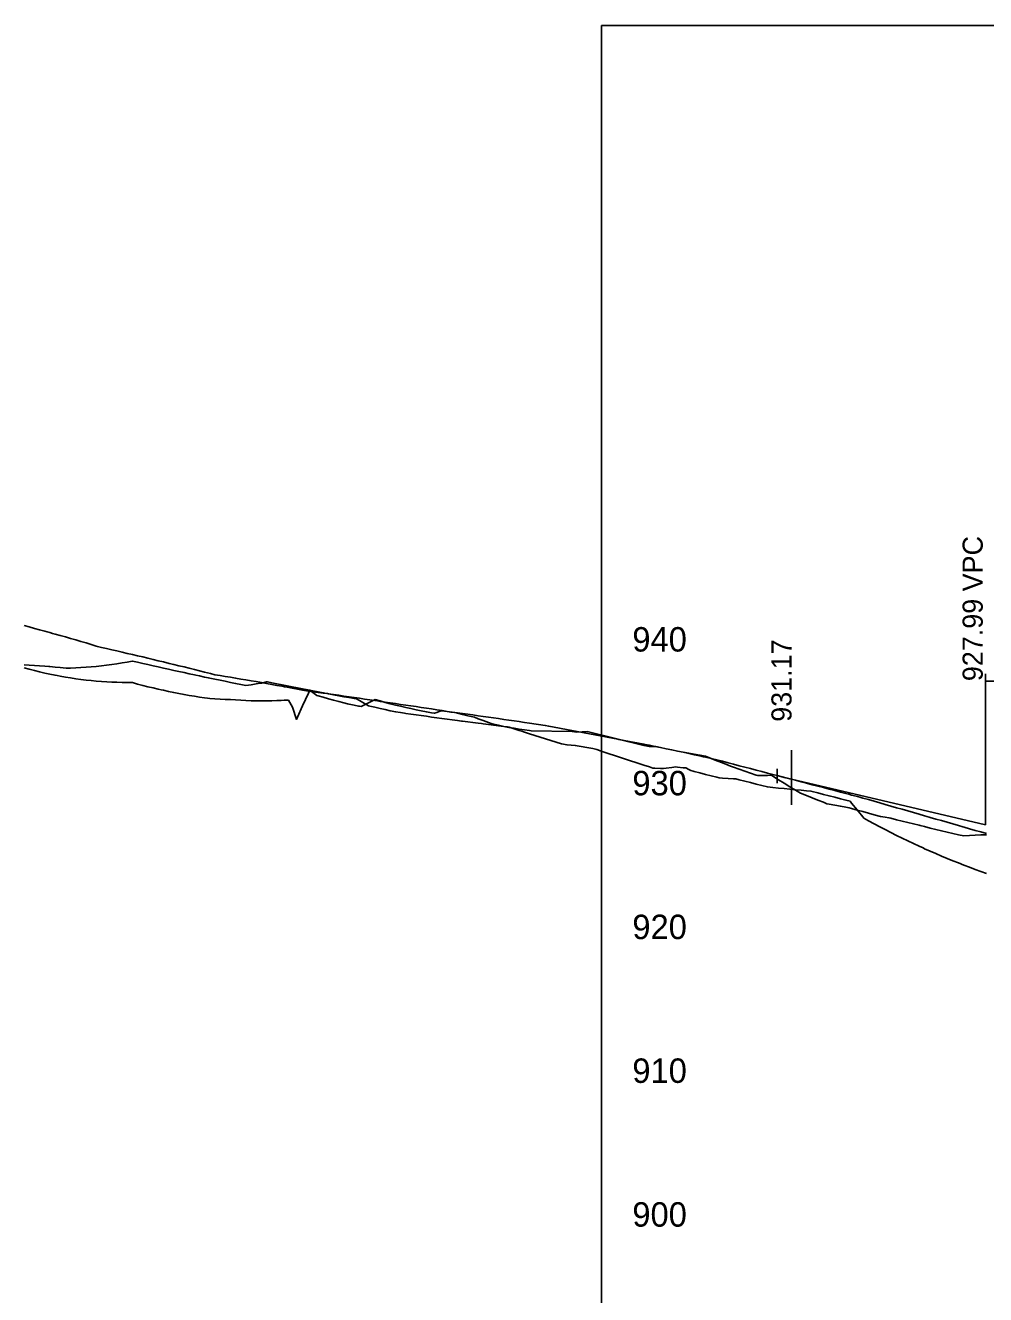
# Model space of a CAD drawing. Extents: x 1538426 to 1542651, y 1162537 to 1163637.
# Drawn here: x 1539359.4 to 1539693.4, y 1163195.3 to 1163636.7 of the extents above; entities that cross this region are included whole.
import ezdxf

# ---------------------------------------------------------------- set-up
doc = ezdxf.new("R2010")
doc.units = 0
for name, color, linetype in [('BR_EXIST_GROUND_LT', 7, 'Continuous'), ('BR_EXIST_GROUND_RT', 7, 'Continuous'), ('BR_USER NOTES', 7, 'Continuous'), ('RD_DDB_ElevTX', 7, 'Continuous'), ('RD_DDB_Profile_EX', 7, 'Continuous'), ('RD_DDB_Profile_Lbl', 7, 'Continuous'), ('RD_DDB_Profile_PR', 7, 'Continuous'), ('RD_DDB_StripGrade', 7, 'Continuous'), ('RD_DDB_VCLbl', 7, 'Continuous'), ('RD_SHT_ShtClip', 7, 'Continuous')]:
    doc.layers.add(name, color=color, linetype=linetype)

msp = doc.modelspace()

# ---------------------------------------------------------------- linework, layer by layer
at = {"layer": 'BR_EXIST_GROUND_LT'}
msp.add_lwpolyline([(1539358.99, 1163414.41), (1539360.78, 1163414.24), (1539362.58, 1163414.09), (1539364.37, 1163413.97), (1539366.16, 1163413.86), (1539367.57, 1163413.8), (1539367.96, 1163413.75), (1539369.75, 1163413.55), (1539371.55, 1163413.37), (1539373.64, 1163413.19), (1539375.14, 1163413.23), (1539376.93, 1163413.29), (1539378.72, 1163413.39), (1539380.52, 1163413.5), (1539382.31, 1163413.64), (1539384.11, 1163413.81), (1539385.9, 1163414), (1539387.69, 1163414.21), (1539389.49, 1163414.45), (1539391.28, 1163414.72), (1539393.08, 1163415.01), (1539394.87, 1163415.32), (1539396.6, 1163415.64), (1539397.27, 1163415.51), (1539398.46, 1163415.24), (1539400.25, 1163414.83), (1539402.05, 1163414.42), (1539403.84, 1163414.02), (1539405.64, 1163413.62), (1539407.43, 1163413.22), (1539409.22, 1163412.83), (1539411.02, 1163412.43), (1539412.81, 1163412.04), (1539414.61, 1163411.66), (1539416.4, 1163411.27), (1539418.2, 1163410.89), (1539418.67, 1163410.79), (1539419.99, 1163410.5), (1539421.78, 1163410.11), (1539423.1, 1163409.83), (1539423.58, 1163409.73), (1539425.37, 1163409.36), (1539427.17, 1163408.99), (1539428.96, 1163408.62), (1539430.75, 1163408.25), (1539432.55, 1163407.89), (1539434.34, 1163407.53), (1539436.14, 1163407.18), (1539437.93, 1163407.44), (1539439.74, 1163407.7), (1539441.2, 1163407.92), (1539441.52, 1163408.03), (1539443.31, 1163408.49), (1539443.67, 1163408.43), (1539445.11, 1163408.15), (1539446.9, 1163407.79), (1539448.7, 1163407.44), (1539450.49, 1163407.09), (1539452.28, 1163406.74), (1539454.08, 1163406.39), (1539455.87, 1163406.04), (1539457.67, 1163405.7), (1539459.46, 1163405.35), (1539461.26, 1163405), (1539463.05, 1163404.66), (1539464.84, 1163404.31), (1539466.64, 1163403.97), (1539468.43, 1163403.62), (1539470.23, 1163403.28), (1539472.02, 1163402.94), (1539473.81, 1163402.64), (1539474.64, 1163402.51), (1539475.61, 1163401.94), (1539477.4, 1163400.9), (1539478.77, 1163400.1), (1539479.2, 1163400.02), (1539480.99, 1163399.61), (1539482.79, 1163399.2), (1539484.58, 1163398.79), (1539486.37, 1163398.38), (1539487.02, 1163398.23), (1539488.17, 1163398.05), (1539489.96, 1163397.75), (1539491.27, 1163397.54), (1539491.76, 1163397.47), (1539493.55, 1163397.21), (1539495.34, 1163396.95), (1539497.14, 1163396.7), (1539498.93, 1163396.45), (1539500.73, 1163396.2), (1539502.52, 1163395.96), (1539504.32, 1163395.71), (1539506.11, 1163395.47), (1539507.9, 1163395.24), (1539509.7, 1163395), (1539511.17, 1163394.81), (1539511.49, 1163394.77), (1539513.29, 1163394.54), (1539515.08, 1163394.32), (1539516.87, 1163394.1), (1539518.09, 1163393.95), (1539518.67, 1163393.87), (1539520.46, 1163393.63), (1539522.26, 1163393.4), (1539524.05, 1163393.18), (1539525.85, 1163392.96), (1539527.1, 1163392.81), (1539527.68, 1163392.67), (1539529.43, 1163392.1), (1539531.23, 1163391.52), (1539532.1, 1163391.24), (1539533.02, 1163390.94), (1539534.82, 1163390.35), (1539545.94, 1163386.89), (1539547.84, 1163386.53), (1539550.66, 1163386.35), (1539556.76, 1163385.2), (1539558.19, 1163384.86), (1539559.71, 1163384.28), (1539574.51, 1163379.5), (1539576.47, 1163378.86), (1539577.7, 1163378.46), (1539578.42, 1163378.43), (1539580.38, 1163378.36), (1539581.41, 1163378.34), (1539582.33, 1163378.43), (1539584.28, 1163378.65), (1539585.73, 1163378.83), (1539586.24, 1163378.77), (1539588.19, 1163378.58), (1539589.18, 1163378.48), (1539590.15, 1163378), (1539590.91, 1163377.62), (1539591.69, 1163377.36), (1539592.1, 1163377.26), (1539594.06, 1163376.76), (1539596.01, 1163376.27), (1539597.96, 1163375.78), (1539599.92, 1163375.27), (1539600.75, 1163375.06), (1539601.87, 1163374.99), (1539603.83, 1163374.87), (1539605.78, 1163374.75), (1539606.52, 1163374.71), (1539607.73, 1163374.39), (1539609.69, 1163373.89), (1539611.64, 1163373.39), (1539613.6, 1163372.89), (1539615.55, 1163372.4), (1539617.51, 1163371.92), (1539619.46, 1163371.72), (1539621.41, 1163371.52), (1539623.37, 1163371.33), (1539625.32, 1163371.13), (1539627.28, 1163370.94), (1539629.23, 1163370.75), (1539631.18, 1163370.57), (1539632.66, 1163370.44), (1539633.14, 1163370.31), (1539635.09, 1163369.8), (1539637.05, 1163369.3), (1539639, 1163368.79), (1539640.96, 1163368.29), (1539642.91, 1163367.79), (1539644.86, 1163367.29), (1539646.26, 1163366.93), (1539646.82, 1163366.26), (1539648.77, 1163363.9), (1539649.2, 1163363.39), (1539650.73, 1163361.48), (1539651.08, 1163361.04), (1539652.68, 1163360.16), (1539654.63, 1163359.11), (1539656.59, 1163358.07), (1539658.54, 1163357.05), (1539660.5, 1163356.05), (1539662.45, 1163355.06), (1539664.41, 1163354.1), (1539666.36, 1163353.15), (1539668.31, 1163352.22), (1539670.27, 1163351.31), (1539671.7, 1163350.66), (1539672.22, 1163350.42), (1539674.18, 1163349.55), (1539676.13, 1163348.69), (1539678.08, 1163347.85), (1539680.04, 1163347.04), (1539681.99, 1163346.24), (1539683.95, 1163345.46), (1539685.9, 1163344.69), (1539687.86, 1163343.95), (1539689.81, 1163343.22), (1539691.76, 1163342.52), (1539693.72, 1163341.83)], dxfattribs=at)
at = {"layer": 'BR_EXIST_GROUND_RT'}
msp.add_lwpolyline([(1539358.99, 1163413.31), (1539360.78, 1163412.82), (1539362.58, 1163412.35), (1539364.37, 1163411.91), (1539366.16, 1163411.5), (1539367.96, 1163411.11), (1539369.75, 1163410.74), (1539370.52, 1163410.59), (1539371.55, 1163410.4), (1539373.34, 1163410.08), (1539375.14, 1163409.79), (1539376.93, 1163409.53), (1539378.72, 1163409.28), (1539380.52, 1163409.06), (1539382.31, 1163408.87), (1539384.11, 1163408.7), (1539385.9, 1163408.55), (1539387.78, 1163408.42), (1539389.49, 1163408.34), (1539391.28, 1163408.27), (1539393.08, 1163408.22), (1539394.87, 1163408.2), (1539396.67, 1163408.16), (1539398.46, 1163407.66), (1539400.25, 1163407.18), (1539402.05, 1163406.73), (1539403.84, 1163406.3), (1539405.64, 1163405.9), (1539406.66, 1163405.68), (1539407.43, 1163405.5), (1539409.22, 1163405.09), (1539411.02, 1163404.71), (1539412.81, 1163404.34), (1539414.61, 1163404.01), (1539416.4, 1163403.69), (1539418.2, 1163403.4), (1539419.99, 1163403.13), (1539421.78, 1163402.88), (1539422.74, 1163402.77), (1539423.58, 1163402.69), (1539425.37, 1163402.55), (1539427.17, 1163402.43), (1539428.96, 1163402.34), (1539430.75, 1163402.27), (1539432.55, 1163402.14), (1539434.34, 1163402.04), (1539436.14, 1163401.95), (1539437.93, 1163401.89), (1539439.73, 1163401.85), (1539441.52, 1163401.83), (1539443.31, 1163401.83), (1539445.11, 1163401.86), (1539446.9, 1163401.9), (1539448.42, 1163401.96), (1539449.4, 1163402.01), (1539450.49, 1163402.08), (1539450.95, 1163402.11), (1539452.38, 1163399.67), (1539453.75, 1163395.38), (1539454.08, 1163396.12), (1539455.87, 1163400.09), (1539457.87, 1163404.53), (1539458.35, 1163405.6), (1539459.46, 1163404.78), (1539460.82, 1163403.72), (1539461.26, 1163403.59), (1539463.05, 1163403.08), (1539464.84, 1163402.58), (1539466.64, 1163402.08), (1539468.43, 1163401.58), (1539470.23, 1163401.09), (1539471.46, 1163400.75), (1539472.02, 1163400.63), (1539473.81, 1163400.27), (1539475.3, 1163399.97), (1539475.61, 1163399.95), (1539476.19, 1163399.91), (1539477.4, 1163400.49), (1539479.2, 1163401.36), (1539481.07, 1163402.28), (1539482.79, 1163401.8), (1539484.58, 1163401.31), (1539486.37, 1163400.83), (1539488.17, 1163400.38), (1539489.96, 1163399.94), (1539491.76, 1163399.52), (1539493.55, 1163399.11), (1539495.34, 1163398.73), (1539497.14, 1163398.35), (1539498.93, 1163398), (1539500.73, 1163397.66), (1539501.73, 1163397.49), (1539502.52, 1163397.75), (1539503.98, 1163398.38), (1539504.32, 1163398.33), (1539506.11, 1163398.07), (1539507.9, 1163397.84), (1539509.4, 1163397.67), (1539509.7, 1163397.58), (1539511.49, 1163397.12), (1539513.29, 1163396.67), (1539515.08, 1163396.25), (1539515.65, 1163396.12), (1539516.87, 1163395.63), (1539518.67, 1163394.94), (1539520.46, 1163394.27), (1539521.4, 1163393.94), (1539522.26, 1163393.74), (1539524.05, 1163393.34), (1539525.85, 1163392.96), (1539527.64, 1163392.61), (1539529.43, 1163392.29), (1539531.23, 1163391.99), (1539533.02, 1163391.72), (1539534.82, 1163391.47), (1539535.3, 1163391.41), (1539549.63, 1163391.21), (1539551.26, 1163390.99), (1539554.8, 1163391.18), (1539574.51, 1163386.33), (1539576.47, 1163385.91), (1539578.7, 1163385.93), (1539580.38, 1163385.57), (1539582.33, 1163385.15), (1539584.28, 1163384.76), (1539586.24, 1163384.37), (1539588.19, 1163384), (1539590.15, 1163383.64), (1539592.1, 1163383.29), (1539594.06, 1163382.96), (1539596.01, 1163382.62), (1539597.96, 1163381.82), (1539599.92, 1163381.02), (1539601.87, 1163380.24), (1539603.83, 1163379.47), (1539604.72, 1163379.13), (1539605.78, 1163378.74), (1539607.73, 1163378.05), (1539609.69, 1163377.36), (1539611.64, 1163376.69), (1539613.6, 1163376.03), (1539614.07, 1163375.88), (1539615.55, 1163375.89), (1539617.51, 1163375.92), (1539618.9, 1163375.95), (1539619.46, 1163375.6), (1539621.41, 1163374.36), (1539623.37, 1163373.15), (1539625.32, 1163371.97), (1539627.28, 1163370.8), (1539629.08, 1163369.76), (1539631.18, 1163368.88), (1539633.14, 1163368.09), (1539635.09, 1163367.31), (1539637.05, 1163366.54), (1539638.25, 1163366.07), (1539639, 1163365.93), (1539640.96, 1163365.56), (1539642.91, 1163365.19), (1539644.86, 1163364.84), (1539645.97, 1163364.65), (1539646.82, 1163364.4), (1539648.77, 1163363.85), (1539650.73, 1163363.31), (1539652.68, 1163362.77), (1539654.63, 1163362.24), (1539656.82, 1163361.66), (1539658.54, 1163361.38), (1539659.8, 1163361.18), (1539660.5, 1163361), (1539662.45, 1163360.5), (1539664.41, 1163360.01), (1539666.36, 1163359.53), (1539668.31, 1163359.06), (1539670.27, 1163358.59), (1539670.64, 1163358.5), (1539672.22, 1163358.1), (1539674.18, 1163357.61), (1539676.13, 1163357.13), (1539678.08, 1163356.66), (1539680.04, 1163356.19), (1539681.99, 1163355.72), (1539683.95, 1163355.27), (1539685.9, 1163354.9), (1539687.86, 1163354.98), (1539689.81, 1163355.08), (1539691.76, 1163355.18), (1539693.72, 1163355.29)], dxfattribs=at)
at = {"layer": 'BR_USER NOTES'}
for p, q in [((1539625.92, 1163384.65), (1539625.92, 1163365.69)), ((1539620.92, 1163378.13), (1539620.92, 1163373.15)), ((1539620.92, 1163375.84), (1539625.92, 1163374.55))]:
    msp.add_line(p, q, dxfattribs=at)
at = {"layer": 'RD_DDB_Profile_EX'}
msp.add_lwpolyline([(1539358.99, 1163428.02), (1539360.78, 1163427.52), (1539362.58, 1163427.03), (1539364.37, 1163426.53), (1539366.16, 1163426.03), (1539367.02, 1163425.79), (1539367.96, 1163425.55), (1539368.89, 1163425.3), (1539369.75, 1163425.06), (1539371.55, 1163424.56), (1539373.34, 1163424.06), (1539375.14, 1163423.55), (1539376.93, 1163423.05), (1539377.68, 1163422.84), (1539378.72, 1163422.52), (1539380.52, 1163421.96), (1539382.31, 1163421.41), (1539384.11, 1163420.85), (1539384.51, 1163420.72), (1539385.9, 1163420.4), (1539387.69, 1163420), (1539389.49, 1163419.59), (1539391.28, 1163419.18), (1539393.08, 1163418.77), (1539394.87, 1163418.35), (1539396.67, 1163417.93), (1539398.46, 1163417.51), (1539400.25, 1163417.09), (1539402.05, 1163416.66), (1539403.84, 1163416.23), (1539405.64, 1163415.8), (1539407.43, 1163415.37), (1539409.5, 1163414.86), (1539411.02, 1163414.49), (1539412.81, 1163414.05), (1539414.61, 1163413.6), (1539416.4, 1163413.15), (1539418.2, 1163412.7), (1539419.99, 1163412.25), (1539421.78, 1163411.79), (1539423.77, 1163411.29), (1539425.37, 1163410.88), (1539427.17, 1163410.6), (1539428.96, 1163410.31), (1539430.75, 1163410.02), (1539432.55, 1163409.72), (1539434.34, 1163409.42), (1539436.14, 1163409.12), (1539437.93, 1163408.81), (1539439.73, 1163408.5), (1539441.52, 1163408.18), (1539443.31, 1163407.86), (1539445.11, 1163407.54), (1539446.9, 1163407.21), (1539448.7, 1163406.88), (1539449.26, 1163406.78), (1539449.59, 1163406.73), (1539450.49, 1163406.56), (1539452.28, 1163406.22), (1539454.08, 1163405.88), (1539455.87, 1163405.54), (1539457.89, 1163405.15), (1539459.46, 1163404.96), (1539461.26, 1163404.75), (1539463.05, 1163404.52), (1539464.46, 1163404.34), (1539464.84, 1163404.29), (1539466.64, 1163404.03), (1539468.43, 1163403.77), (1539470.23, 1163403.51), (1539472.02, 1163403.25), (1539473.81, 1163402.99), (1539475.61, 1163402.73), (1539477.4, 1163402.47), (1539479.2, 1163402.21), (1539480.99, 1163401.94), (1539481.92, 1163401.81), (1539482.86, 1163401.65), (1539484.58, 1163401.4), (1539486.37, 1163401.14), (1539488.17, 1163400.87), (1539489.96, 1163400.61), (1539491.76, 1163400.34), (1539493.55, 1163400.07), (1539495.34, 1163399.81), (1539497.14, 1163399.54), (1539498.93, 1163399.27), (1539500.73, 1163399), (1539502.52, 1163398.73), (1539504.45, 1163398.45), (1539506.11, 1163398.16), (1539507.38, 1163397.94), (1539507.9, 1163397.88), (1539509.7, 1163397.64), (1539511.49, 1163397.4), (1539513.29, 1163397.16), (1539515.08, 1163396.92), (1539516.87, 1163396.67), (1539518.67, 1163396.42), (1539520.46, 1163396.17), (1539522.26, 1163395.92), (1539524.05, 1163395.66), (1539525.85, 1163395.4), (1539527.64, 1163395.14), (1539529.43, 1163394.88), (1539531.23, 1163394.61), (1539532.34, 1163394.44), (1539533.02, 1163394.35), (1539534.82, 1163394.08), (1539540.23, 1163393.26), (1539541.48, 1163393.01), (1539565.46, 1163388.48), (1539565.82, 1163388.41), (1539574.51, 1163386.77), (1539574.88, 1163386.7), (1539576.47, 1163386.38), (1539578.42, 1163385.97), (1539580.38, 1163385.57), (1539582.33, 1163385.16), (1539584.28, 1163384.76), (1539586.24, 1163384.34), (1539588.19, 1163383.93), (1539590.15, 1163383.51), (1539592.1, 1163383.09), (1539594.06, 1163382.67), (1539595.34, 1163382.39), (1539596.01, 1163382.23), (1539597.96, 1163381.76), (1539599.92, 1163381.3), (1539600.43, 1163381.17), (1539601.87, 1163380.8), (1539603.83, 1163380.29), (1539605.78, 1163379.78), (1539607.73, 1163379.27), (1539609.69, 1163378.76), (1539611.64, 1163378.25), (1539613.6, 1163377.74), (1539615.55, 1163377.22), (1539617.51, 1163376.71), (1539619.46, 1163376.2), (1539621.41, 1163375.72), (1539623.37, 1163375.21), (1539625.32, 1163374.7), (1539627.28, 1163374.19), (1539629.23, 1163373.68), (1539631.18, 1163373.17), (1539633.14, 1163372.66), (1539635.09, 1163372.15), (1539637.05, 1163371.64), (1539639, 1163371.12), (1539640.96, 1163370.61), (1539642.91, 1163370.1), (1539644.86, 1163369.58), (1539645.84, 1163369.34), (1539646.82, 1163369.08), (1539648.81, 1163368.56), (1539649.71, 1163368.31), (1539650.73, 1163368.02), (1539652.68, 1163367.47), (1539654.63, 1163366.91), (1539656.59, 1163366.35), (1539658.54, 1163365.8), (1539660.5, 1163365.24), (1539662.45, 1163364.68), (1539664.41, 1163364.12), (1539666.36, 1163363.56), (1539668.31, 1163363), (1539670.27, 1163362.43), (1539672.22, 1163361.87), (1539673.77, 1163361.42), (1539674.18, 1163361.31), (1539676.13, 1163360.74), (1539678.08, 1163360.18), (1539680.04, 1163359.61), (1539681.99, 1163359.05), (1539683.95, 1163358.48), (1539685.5, 1163358.03), (1539686.01, 1163357.89), (1539687.86, 1163357.35), (1539689.81, 1163356.78), (1539691.76, 1163356.22), (1539693.72, 1163355.65)], dxfattribs=at)
at = {"layer": 'RD_DDB_Profile_PR'}
msp.add_line((1539625.92, 1163374.55), (1539693.42, 1163358.68), dxfattribs=at)
at = {"layer": 'RD_DDB_VCLbl'}
for p, q in [((1539693.42, 1163411.18), (1539693.42, 1163358.68)), ((1539693.42, 1163408.68), (1540068.42, 1163408.68))]:
    msp.add_line(p, q, dxfattribs=at)
at = {"layer": 'RD_SHT_ShtClip'}
for p, q in [((1539559.8, 1163636.73), (1541409.8, 1163636.73)), ((1539559.8, 1162536.73), (1539559.8, 1163636.73))]:
    msp.add_line(p, q, dxfattribs=at)

# ---------------------------------------------------------------- texts
at = {"layer": 'RD_DDB_ElevTX'}
for s, p in [('940', (1539570.55, 1163418.97)), ('930', (1539570.55, 1163368.97)), ('920', (1539570.55, 1163318.97)), ('910', (1539570.55, 1163268.97)), ('900', (1539570.55, 1163218.97))]:
    msp.add_text(s, height=8.5, dxfattribs=at).set_placement(p)
at = {"layer": 'RD_DDB_Profile_Lbl'}
msp.add_text('931.17', height=7, rotation=90, dxfattribs=at).set_placement((1539625.92, 1163394.55))
at = {"layer": 'RD_DDB_StripGrade'}
msp.add_text('927.99 VPC', height=7, rotation=90, dxfattribs=at).set_placement((1539692.42, 1163408.68))

doc.saveas('drawing.dxf')
